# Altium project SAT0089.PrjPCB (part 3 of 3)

## Sheet CAMERA 6.SchDoc
size 431 x 279 mm; Date: Not shown in title block; ApprovedBy: Not shown in title block; CheckedBy: Not shown in title block; Author: Not shown in title block; CompanyName: Not shown in title block; DrawnBy: G. Fiolic; Engineer: Not shown in title block; Organization: Not shown in title block; Address1: Not shown in title block; Address2: Not shown in title block; Address3: Not shown in title block; Address4: Not shown in title block; DocumentNumber: 10; Revision: Use project parameter SCH_Rev; SheetNumber: 10; SheetTotal: 11; PageSetup: Record=PageOptions|CenterHorizontal=True|CenterVertical=True|PrintScale=1.00|XCorrection=1.00|YCorrection=1.00|PrintKind=0|BorderSize=5000000|LeftOffset=0|BottomOffset=0|Orientation=2|PaperLength=1000|PaperWidth=1000|Scale=100|PaperSource=15|PrintQuality=600|MediaType=1|DitherType=10|PaperKind=Letter|PrintScaleMode=1
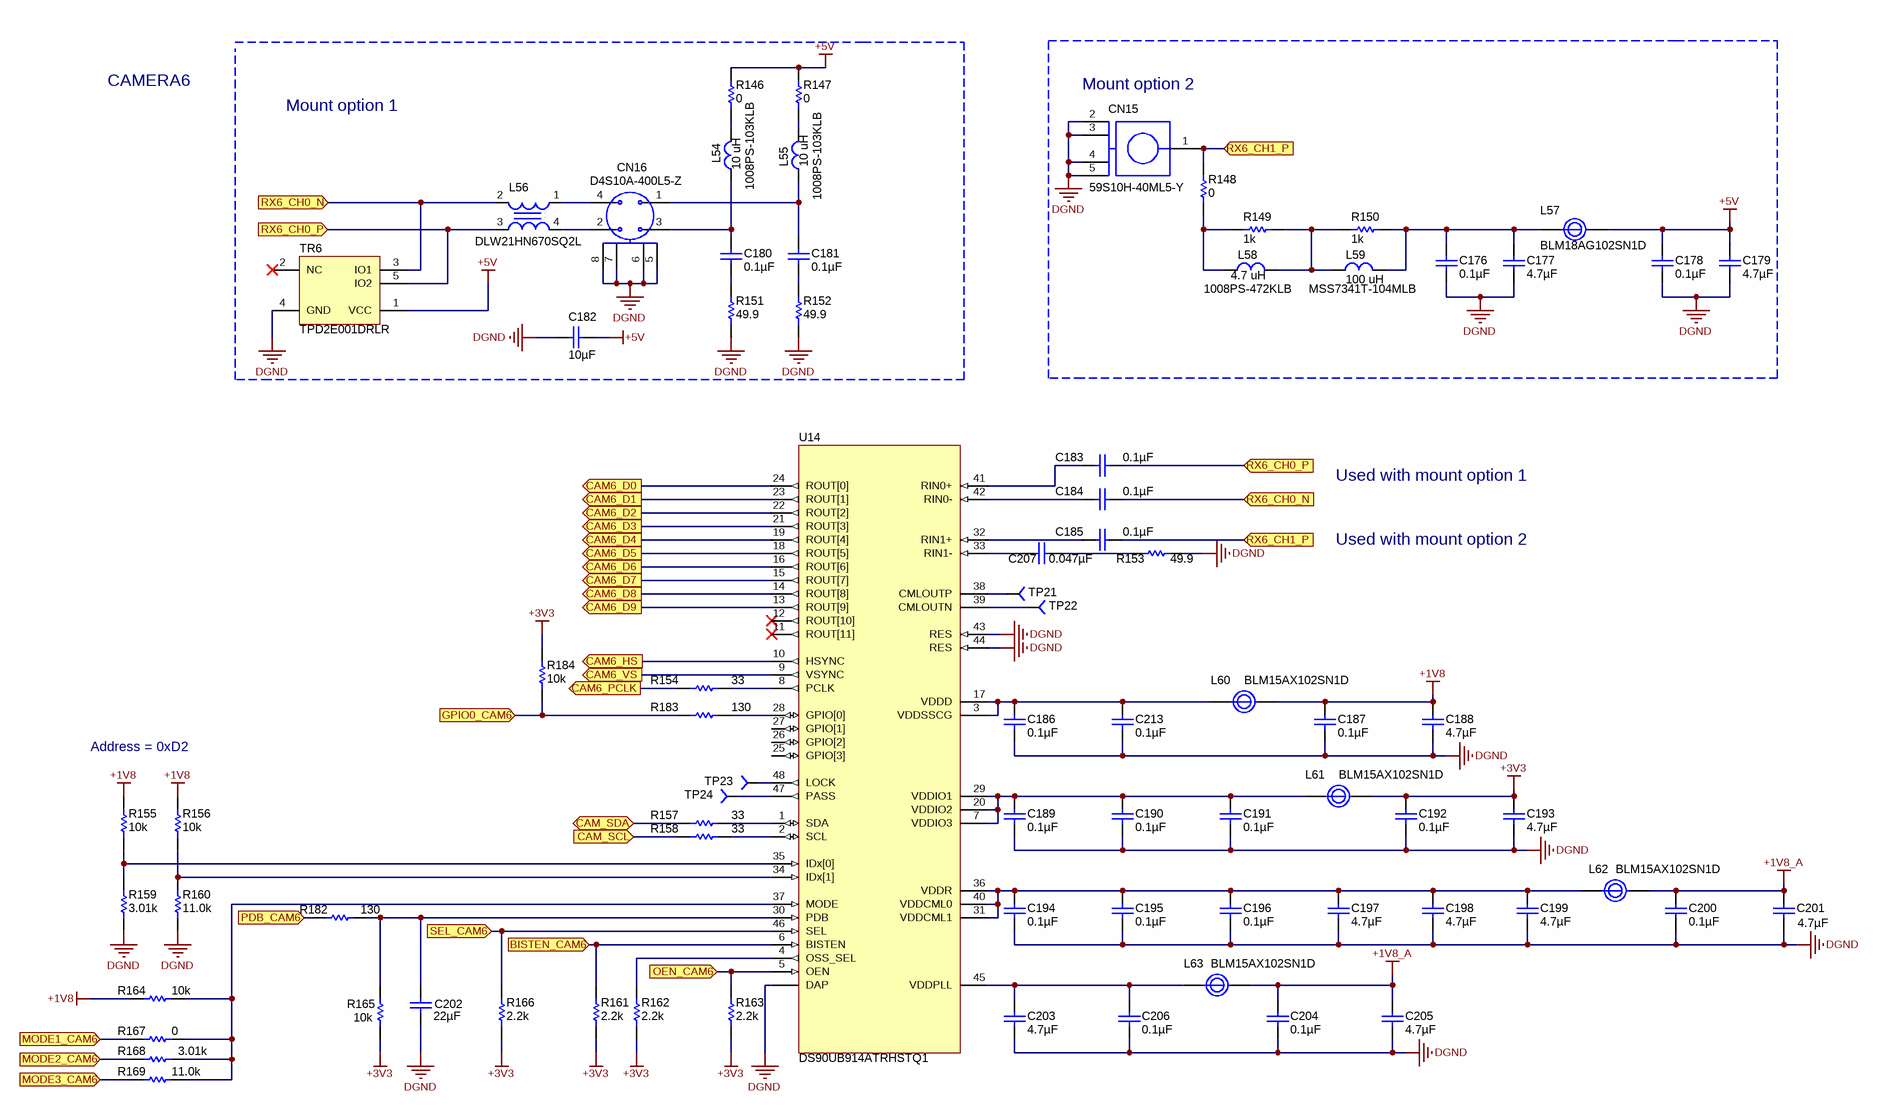
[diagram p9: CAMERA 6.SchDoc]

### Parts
C176  ValueDisplayed: 0.1µF  [0402L]  (hidden comment: GRM155R71C104KA88D)
C177  value 4.7µF  [0603L]  (hidden comment: GRM188R61E475KE11D)
C178  ValueDisplayed: 0.1µF  [0402L]  (hidden comment: GRM155R71C104KA88D)
C179  value 4.7µF  [0603L]  (hidden comment: GRM188R61E475KE11D)
C180  value 0.1µF  [0603L]  (hidden comment: GRM188R72A104KA35D)
C181  value 0.1µF  [0603L]  (hidden comment: GRM188R72A104KA35D)
C182  ValueDisplayed: 10µF  [0805L]  (hidden comment: GRM21BR61C106KE15L)
C183  ValueDisplayed: 0.1µF  [0402L]  (hidden comment: GRM155R71C104KA88D)
C184  ValueDisplayed: 0.1µF  [0402L]  (hidden comment: GRM155R71C104KA88D)
C185  ValueDisplayed: 0.1µF  [0402L]  (hidden comment: GRM155R71C104KA88D)
C186  ValueDisplayed: 0.1µF  [0402L]  (hidden comment: GRM155R71C104KA88D)
C187  ValueDisplayed: 0.1µF  [0402L]  (hidden comment: GRM155R71C104KA88D)
C188  value 4.7µF  [0603L]  (hidden comment: GRM188R61E475KE11D)
C189  ValueDisplayed: 0.1µF  [0402L]  (hidden comment: GRM155R71C104KA88D)
C190  ValueDisplayed: 0.1µF  [0402L]  (hidden comment: GRM155R71C104KA88D)
C191  ValueDisplayed: 0.1µF  [0402L]  (hidden comment: GRM155R71C104KA88D)
C192  ValueDisplayed: 0.1µF  [0402L]  (hidden comment: GRM155R71C104KA88D)
C193  value 4.7µF  [0603L]  (hidden comment: GRM188R61E475KE11D)
C194  ValueDisplayed: 0.1µF  [0402L]  (hidden comment: GRM155R71C104KA88D)
C195  ValueDisplayed: 0.1µF  [0402L]  (hidden comment: GRM155R71C104KA88D)
C196  ValueDisplayed: 0.1µF  [0402L]  (hidden comment: GRM155R71C104KA88D)
C197  value 4.7µF  [0603L]  (hidden comment: GRM188R61E475KE11D)
C198  value 4.7µF  [0603L]  (hidden comment: GRM188R61E475KE11D)
C199  value 4.7µF  [0603L]  (hidden comment: GRM188R61E475KE11D)
C200  ValueDisplayed: 0.1µF  [0402L]  (hidden comment: GRM155R71C104KA88D)
C201  value 4.7µF  [0603L]  (hidden comment: GRM188R61E475KE11D)
C202  ValueDisplayed: 22µF  [0805L]  (hidden comment: JMK212BJ226KG-T)
C203  value 4.7µF  [0603L]  (hidden comment: GRM188R61E475KE11D)
C204  ValueDisplayed: 0.1µF  [0402L]  (hidden comment: GRM155R71C104KA88D)
C205  value 4.7µF  [0603L]  (hidden comment: GRM188R61E475KE11D)
C206  ValueDisplayed: 0.1µF  [0402L]  (hidden comment: GRM155R71C104KA88D)
C207  ValueDisplayed: 0.047µF  [0402L]  (hidden comment: GRM155R71C473KA01D)
C213  ValueDisplayed: 0.1µF  [0402L]  (hidden comment: GRM155R71C104KA88D)
CN15  59S10H-40ML5-Y  [59S10H-40ML5-Y]
CN16  D4S10A-400L5-Z  [D4S10A-400L5-Z]
L54  1008PS-103KLB  ValueDisplayed: 10 uH  [1008PS-103KLB]
L55  1008PS-103KLB  ValueDisplayed: 10 uH  [1008PS-103KLB]
L56  DLW21HN670SQ2L  [DLW21HN670SQ2L]
L57  BLM18AG102SN1D  [0603L]
L58  ValueDisplayed: 4.7 uH  [1008PS-472KLB]  (hidden comment: 1008PS-472KLB)
L59  ValueDisplayed: 100 uH  [MSS7341T-104MLB]  (hidden comment: MSS7341T-104MLB)
L60  BLM15AX102SN1D  [0402L]
L61  BLM15AX102SN1D  [0402L]
L62  BLM15AX102SN1D  [0402L]
L63  BLM15AX102SN1D  [0402L]
R146  value 0  [0805L]  (hidden comment: CRCW08050000Z0EA)
R147  value 0  [0805L]  (hidden comment: CRCW08050000Z0EA)
R148  value 0  [0805L]  (hidden comment: CRCW08050000Z0EA)
R149  value 1k  [0603L]  (hidden comment: RC0603JR-071KL)
R150  value 1k  [0603L]  (hidden comment: RC0603JR-071KL)
R151  value 49.9  [0402L]  (hidden comment: CRCW040249R9FKED)
R152  value 49.9  [0402L]  (hidden comment: CRCW040249R9FKED)
R153  value 49.9  [0402L]  (hidden comment: CRCW040249R9FKED)
R154  value 33  [0402L]  (hidden comment: CRCW040233R0JNED)
R155  value 10k  [0402L]  (hidden comment: ERA-2AEB103X)
R156  value 10k  [0402L]  (hidden comment: ERA-2AEB103X)
R157  value 33  [0402L]  (hidden comment: CRCW040233R0JNED)
R158  value 33  [0402L]  (hidden comment: CRCW040233R0JNED)
R159  value 3.01k  [0402L]  (hidden comment: CRCW04023K01FKED)
R160  value 11.0k  [0402L]  (hidden comment: CRCW040211K0FKED)
R161  value 2.2k  [0402L]  (hidden comment: CRCW04022K20JNED)
R162  value 2.2k  [0402L]  (hidden comment: CRCW04022K20JNED)
R163  value 2.2k  [0402L]  (hidden comment: CRCW04022K20JNED)
R164  value 10k  [0402L]  (hidden comment: ERA-2AEB103X)
R165  value 10k  [0402L]  (hidden comment: ERA-2AEB103X)
R166  value 2.2k  [0402L]  (hidden comment: CRCW04022K20JNED)
R167  value 0  [0402L]  (hidden comment: CRCW04020000Z0ED)
R168  value 3.01k  [0402L]  (hidden comment: CRCW04023K01FKED)
R169  value 11.0k  [0402L]  (hidden comment: CRCW040211K0FKED)
R182  value 130  [0402L]  (hidden comment: CRCW0402130RJNED)
R183  value 130  [0402L]  (hidden comment: CRCW0402130RJNED)
R184  value 10k  [0402L]  (hidden comment: ERA-2AEB103X)
TP21  STD  [TP-032_RND]  (value not drawn)
TP22  STD  [TP-032_RND]  (value not drawn)
TP23  STD  [TP-032_RND]  (value not drawn)
TP24  STD  [TP-032_RND]  (value not drawn)
TR6  TPD2E001DRLR  [DRL0005A]
U14  DS90UB914ATRHSTQ1  [RHS0048A]

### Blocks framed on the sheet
Mount option 2: C176-C179 CN15 L57-L59 R148-R150

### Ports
BISTEN_CAM6, CAM6_D0, CAM6_D1, CAM6_D2, CAM6_D3, CAM6_D4, CAM6_D5, CAM6_D6, CAM6_D7, CAM6_D8, CAM6_D9, CAM6_HS, CAM6_PCLK, CAM6_VS, CAM_SCL, CAM_SDA, GPIO0_CAM6, MODE1_CAM6, MODE2_CAM6, MODE3_CAM6, OEN_CAM6, PDB_CAM6, RX6_CH0_N, RX6_CH0_P, RX6_CH1_P, SEL_CAM6

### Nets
+1V8: C187.1 C188.1 L60.2 R155.1 R156.1 R164.1
+1V8_A: C200.1 C201.1 C204.1 C205.1 L62.2 L63.2
+3V3: C192.1 C193.1 L61.2 R161.2 R162.2 R163.2 R165.1 R166.1 R184.1
+5V: C178.1 C179.1 C182.1 L57.2 R146.2 R147.2 TR6.1(VCC)
DGND: C176.2 C177.2 C178.2 C179.2 C182.2 C186.2 C187.2 C188.2 C189.2 C190.2 C191.2 C192.2 C193.2 C194.2 C195.2 C196.2 C197.2 C198.2 C199.2 C200.2 C201.2 C202.2 C203.2 C204.2 C205.2 C206.2 C213.2 CN15.2 CN15.3 CN15.4 CN15.5 CN16.5 CN16.6 CN16.7 CN16.8 R151.1 R152.1 R153.2 R159.2 R160.2 TR6.4(GND) U14.43(RES) U14.44(RES) U14.49(DAP)
BISTEN_CAM6: R161.1 U14.6(BISTEN) ; port BISTEN_CAM6
CAM6_D0: U14.24(ROUT[0]) ; port CAM6_D0
CAM6_D1: U14.23(ROUT[1]) ; port CAM6_D1
CAM6_D2: U14.22(ROUT[2]) ; port CAM6_D2
CAM6_D3: U14.21(ROUT[3]) ; port CAM6_D3
CAM6_D4: U14.19(ROUT[4]) ; port CAM6_D4
CAM6_D5: U14.18(ROUT[5]) ; port CAM6_D5
CAM6_D6: U14.16(ROUT[6]) ; port CAM6_D6
CAM6_D7: U14.15(ROUT[7]) ; port CAM6_D7
CAM6_D8: U14.14(ROUT[8]) ; port CAM6_D8
CAM6_D9: U14.13(ROUT[9]) ; port CAM6_D9
CAM6_HS: U14.10(HSYNC) ; port CAM6_HS
CAM6_PCLK: R154.1 ; port CAM6_PCLK
CAM6_VS: U14.9(VSYNC) ; port CAM6_VS
CAM_SCL: R158.1 ; port CAM_SCL
CAM_SDA: R157.2 ; port CAM_SDA
GPIO0_CAM6: R183.1 R184.2 ; port GPIO0_CAM6
MODE1_CAM6: R167.1 ; port MODE1_CAM6
MODE2_CAM6: R168.1 ; port MODE2_CAM6
MODE3_CAM6: R169.1 ; port MODE3_CAM6
OEN_CAM6: R163.1 U14.5(OEN) ; port OEN_CAM6
PDB_CAM6: R182.1 ; port PDB_CAM6
RX6_CH0_N: C184.2 L56.2(IN2) TR6.3(IO1) ; port RX6_CH0_N
RX6_CH0_P: C183.2 L56.3(OUT2) TR6.5(IO2) ; port RX6_CH0_P
RX6_CH1_P: C185.2 CN15.1 R148.2 ; port RX6_CH1_P
SEL_CAM6: R166.2 U14.46(SEL) ; port SEL_CAM6
NetC176_1: C176.1 C177.1 L57.1 L59.2 R150.2
NetC180_1: C180.1 CN16.3 L54.2
NetC180_2: C180.2 R151.2
NetC181_1: C181.1 CN16.1 L55.2
NetC181_2: C181.2 R152.2
NetC183_1: C183.1 U14.41(RIN0+)
NetC184_1: C184.1 U14.42(RIN0-)
NetC185_1: C185.1 U14.32(RIN1+)
NetC186_1: C186.1 C213.1 L60.1 U14.3(VDDSSCG) U14.17(VDDD)
NetC189_1: C189.1 C190.1 C191.1 L61.1 U14.7(VDDIO3) U14.20(VDDIO2) U14.29(VDDIO1)
NetC194_1: C194.1 C195.1 C196.1 C197.1 C198.1 C199.1 L62.1 U14.31(VDDCML1) U14.36(VDDR) U14.40(VDDCML0)
NetC202_1: C202.1 R165.2 R182.2 U14.30(PDB)
NetC203_1: C203.1 C206.1 L63.1 U14.45(VDDPLL)
NetC207_1: C207.1 U14.33(RIN1-)
NetC207_2: C207.2 R153.1
NetCN16_2: CN16.2 L56.4(OUT1)
NetCN16_4: CN16.4 L56.1(IN1)
NetL54_1: L54.1 R146.1
NetL55_1: L55.1 R147.1
NetL58_1: L58.1 R148.1 R149.1
NetL58_2: L58.2 L59.1 R149.2 R150.1
NetR154_2: R154.2 U14.8(PCLK)
NetR155_2: R155.2 R159.1 U14.35(IDx[0])
NetR156_2: R156.2 R160.1 U14.34(IDx[1])
NetR157_1: R157.1 U14.1(SDA)
NetR158_2: R158.2 U14.2(SCL)
NetR162_1: R162.1 U14.4(OSS_SEL)
NetR164_2: R164.2 R167.2 R168.2 R169.2 U14.37(MODE)
NetR183_2: R183.2 U14.28(GPIO[0])
NetTP21_1: TP21.1 U14.38(CMLOUTP)
NetTP22_1: TP22.1 U14.39(CMLOUTN)
NetTP23_1: TP23.1 U14.48(LOCK)
NetTP24_1: TP24.1 U14.47(PASS)

Not connected (* = marked no-connect by the designer): TR6 2(NC)*; U14 11(ROUT[11])* 12(ROUT[10])* 25(GPIO[3]) 26(GPIO[2]) 27(GPIO[1])

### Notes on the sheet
- CAMERA6
- Mount option 1
- Used with mount option 1
- Used with mount option 2
- Address = 0xD2

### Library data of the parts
C176 C178 C183-C187 C189-C192 C194-C196 C200 C204 C206 C213 = GRM155R71C104KA88D: CAP, CERM, 0.1uF, 16V, +/-10%, X7R, 0402; Manufacturer: MuRata; Polarized: N; CompType: Capacitor; U/M: EA; Cap_F: 0.0000001; Tolerance_%: 10; Value1: Unknown; VDC_V: 16; TaMin_C: -55; TaMax_C: 125; Cap_Case: 0402
C177 C179 C188 C193 C197-C199 C201 C203 C205 = GRM188R61E475KE11D: CAP CER 4.7UF 25V 10% X5R 0603; Manufacturer: Murata Electronics North America
C180 C181 = GRM188R72A104KA35D: CAP CER 0.1UF 100V 10% X7R 0603; Manufacturer: Murata Electronics North America
C182 = GRM21BR61C106KE15L: CAP, CERM, 10uF, 16V, +/-10%, X5R, 0805; Manufacturer: MuRata; Polarized: N; CompType: Capacitor; U/M: EA; Cap_F: 0.00001; Tolerance_%: 10; ESR_Ohm: 0.008; Value1: 0.008 ohm; VDC_V: 16; TaMin_C: -55; TaMax_C: 85; Cap_Case: 0805
C202 = JMK212BJ226KG-T: CAP, CERM, 22uF, 6.3V, +/-10%, X5R, 0805; Manufacturer: Taiyo Yuden; Polarized: N; CompType: Capacitor; U/M: EA; Cap_F: 0.000022; Tolerance_%: 10; ESR_Ohm: 0.002; Value1: 0.002 ohm; VDC_V: 6.3; TaMin_C: -55; TaMax_C: 85; Cap_Case: 0805
C207 = GRM155R71C473KA01D: CAP, CERM, 0.047uF, 16V, +/-10%, X7R, 0402; Manufacturer: MuRata; Polarized: N; CompType: Capacitor; U/M: EA; Cap_F: 0.000000047; Tolerance_%: 10; Value1: Unknown; VDC_V: 16; TaMin_C: -55; TaMax_C: 125; Cap_Case: 0402
CN15 = 59S10H-40ML5-Y: Straight Plug PCB; Manufacturer: Rosenberger; SymbolVersion: use current date i.e. 2008-05-20; SymbolCreator: Use a-id; CompType: SMA connector; U/M: EA, IN, or GM
CN16 = D4S10A-400L5-Z: Straight Plug; Manufacturer: Rosenberger
L54 L55 = 1008PS-103KLB: Fixed Inductors Power Inductor 10 uH 10 % 0.59 A; Manufacturer: Coilcraft; Material: Ferrite; Maximum DC Current: 590 mA; Maximum DC Resistance: 920 mOhms; Q Minimum: 38; Self Resonant Frequency: 105 MHz; Shielding: Shielded; Tolerance_%: 10 %; Case Height: 2.74 mm; Case Length: 3.81 mm; Case Width: 3.78 mm; Test Frequency: 100 kHz; Product Status: New at Mouser
L56 = DLW21HN670SQ2L: CHOKE COMMON MODE 67 OHM 0805; Manufacturer: Murata Electronics North America; Filter Type: Data, Signal Line; Number of Lines: 2; Irms: 330mA; DCR_Ohm: 350 mOhm Max; Impedance: 67 Ohm
L57 = BLM18AG102SN1D: FERRITE CHIP 1000 OHM 400MA 0603; Manufacturer: Murata Electronics North America; Impedance @ Frequency: 1 kOhm @ 100MHz; DCR_Ohm: 500 mOhm Max; Filter Type: Differential Mode - Single
L58 = 1008PS-472KLB: Fixed Inductors Power Inductor 4.7 uH 10 % 0.95 A; Manufacturer: Coilcraft; Material: Ferrite; Maximum DC Current: 950 mA; Maximum DC Resistance: 350 mOhms; Q Minimum: 38; Self Resonant Frequency: 160 MHz; Shielding: Shielded; Tolerance_%: 10 %; Case Height: 2.74 mm; Case Length: 3.81 mm; Case Width: 3.78 mm; Test Frequency: 100 kHz
L59 = MSS7341T-104MLB: Fixed Inductors Power Inductor 100 uH 20 % 1.15 A; Manufacturer: Coilcraft; Material: Ferrite; Maximum DC Current: 1.15 A; Maximum DC Resistance: 310 mOhms; Self Resonant Frequency: 7.2 MHz; Shielding: Shielded; Tolerance_%: 20 %; Case Height: 4.1 mm; Case Length: 7.3 mm; Test Frequency: 100 kHz
L60-L63 = BLM15AX102SN1D: FERRITE CHIP 1000 OHM 0402; Manufacturer: Murata Electronics North America; Impedance @ Frequency: 1 kOhm @ 100MHz; Current Rating: 350mA; DCR_Ohm: 490 mOhm Max; Filter Type: Differential Mode - Single
R146-R148 = CRCW08050000Z0EA: RES, 0 ohm, 5%, 0.125W, 0805; Manufacturer: Vishay-Dale; CompType: Resistor; Value_Code: 0000; Tolerance_%: 5; Power_W: 0.125; VDC_V: 150; TempCo: 200 ppm/C; EIA_Code: E24; U/M: EA
R149 R150 = RC0603JR-071KL: RES 1.0K OHM 1/10W 5% 0603 SMD; Manufacturer: Yageo; Power_W: 0.1W, 1/10W; TempCo: ±100ppm/°C
R151-R153 = CRCW040249R9FKED: RES, 49.9 ohm, 1%, 0.063W, 0402; Manufacturer: Vishay-Dale; CompType: Resistor; Value_Code: 49R9; Tolerance_%: 1; Power_W: 0.063; VDC_V: 50; TempCo: 100 ppm/C; EIA_Code: E96; U/M: EA
R154 R157 R158 = CRCW040233R0JNED: RES, 33 ohm, 5%, 0.063W, 0402; Manufacturer: Vishay-Dale; CompType: Resistor; Value_Code: 33R0; Tolerance_%: 5; Power_W: 0.063; VDC_V: 50; TempCo: 200 ppm/C; EIA_Code: E24; U/M: EA
R155 R156 R164 R165 R184 = ERA-2AEB103X: RES 10K OHM 1/16W .1% 0402 SMD; Manufacturer: Panasonic Electronic Components; Tolerance_%: ±0.1%; Power_W: 0.063W, 1/16W; TempCo: ±25ppm/°C
R159 R168 = CRCW04023K01FKED: RES, 3.01k ohm, 1%, 0.063W, 0402; Manufacturer: Vishay-Dale; CompType: Resistor; Res_ohm: 3010; Value_Code: 3k01; Tolerance_%: 1; Power_W: 0.063; VDC_V: 50; TempCo: 100 ppm/C; EIA_Code: E96; U/M: EA
R160 R169 = CRCW040211K0FKED: RES, 11.0k ohm, 1%, 0.063W, 0402; Manufacturer: Vishay-Dale; CompType: Resistor; Res_ohm: 11000; Value_Code: 11k0; Tolerance_%: 1; Power_W: 0.063; VDC_V: 50; TempCo: 100 ppm/C; EIA_Code: E96; U/M: EA
R161-R163 R166 = CRCW04022K20JNED: RES, 2.2k ohm, 5%, 0.063W, 0402; Manufacturer: Vishay-Dale; CompType: Resistor; Res_ohm: 2200; Value_Code: 2k20; Tolerance_%: 5; Power_W: 0.063; VDC_V: 50; TempCo: 200 ppm/C; EIA_Code: E24; U/M: EA
R167 = CRCW04020000Z0ED: RES, 0 ohm, 5%, 0.063W, 0402; Manufacturer: Vishay-Dale; CompType: Resistor; Value_Code: 0000; Tolerance_%: 5; Power_W: 0.063; VDC_V: 50; TempCo: 200 ppm/C; EIA_Code: E24; U/M: EA
R182 R183 = CRCW0402130RJNED: RES, 130 ohm, 5%, 0.063W, 0402; Manufacturer: Vishay-Dale; CompType: Resistor; Value_Code: 130R; Tolerance_%: 5; Power_W: 0.063; VDC_V: 50; TempCo: 200 ppm/C; EIA_Code: E24; U/M: EA
TP21-TP24 = TP-032_RND: Test Point, O.032 Hole
TR6 = TPD2E001DRLR: Low-Capacitance + / - 15 kV ESD-Protection Array for High-Speed Data Interfaces, 2 Channels, -40 to +85 degC, 5-pin SOT (DRL), Green (RoHS & no Sb/Br); Manufacturer: Texas Instruments; Alternate Manufacturer: None; Alternate PartNumber: Equivalent; Breakdown Voltage(Min)(V): 11; IEC 61000-4-2 Air-Gap(+/- kV): 15; IEC 61000-4-2 Contact(+/- kV): 8; IO Capacitance(Typ)(pF): 1.5; IO Leakage Current(nA): 1; SubFamily: ESD Solution; USB High Speed: TRUE
U14 = DS90UB914ATRHSTQ1: FPD-Link III Serializer and Deserializer, RHS0048A; Alternate Manufacturer: None; Manufacturer: Texas Instruments; SymbolCreator: a0799628; CompType: IC; U/M: EA

## Sheet Hardware_ANSI-B.SchDoc
size 431 x 279 mm; Date: Not shown in title block; ApprovedBy: Not shown in title block; CheckedBy: Not shown in title block; Author: Not shown in title block; CompanyName: Not shown in title block; DrawnBy: G. Fiolic; Engineer: Not shown in title block; Organization: Not shown in title block; Address1: Not shown in title block; Address2: Not shown in title block; Address3: Not shown in title block; Address4: Not shown in title block; DocumentNumber: 11; Revision: Use project parameter SCH_Rev; SheetNumber: 11; SheetTotal: 11; PageSetup: Record=PageOptions|CenterHorizontal=True|CenterVertical=True|PrintScale=1.00|XCorrection=1.00|YCorrection=1.00|PrintKind=0|BorderSize=5000000|LeftOffset=0|BottomOffset=0|Orientation=2|PaperLength=1000|PaperWidth=1000|Scale=100|PaperSource=15|PrintQuality=600|MediaType=1|DitherType=10|PaperKind=Letter|PrintScaleMode=1
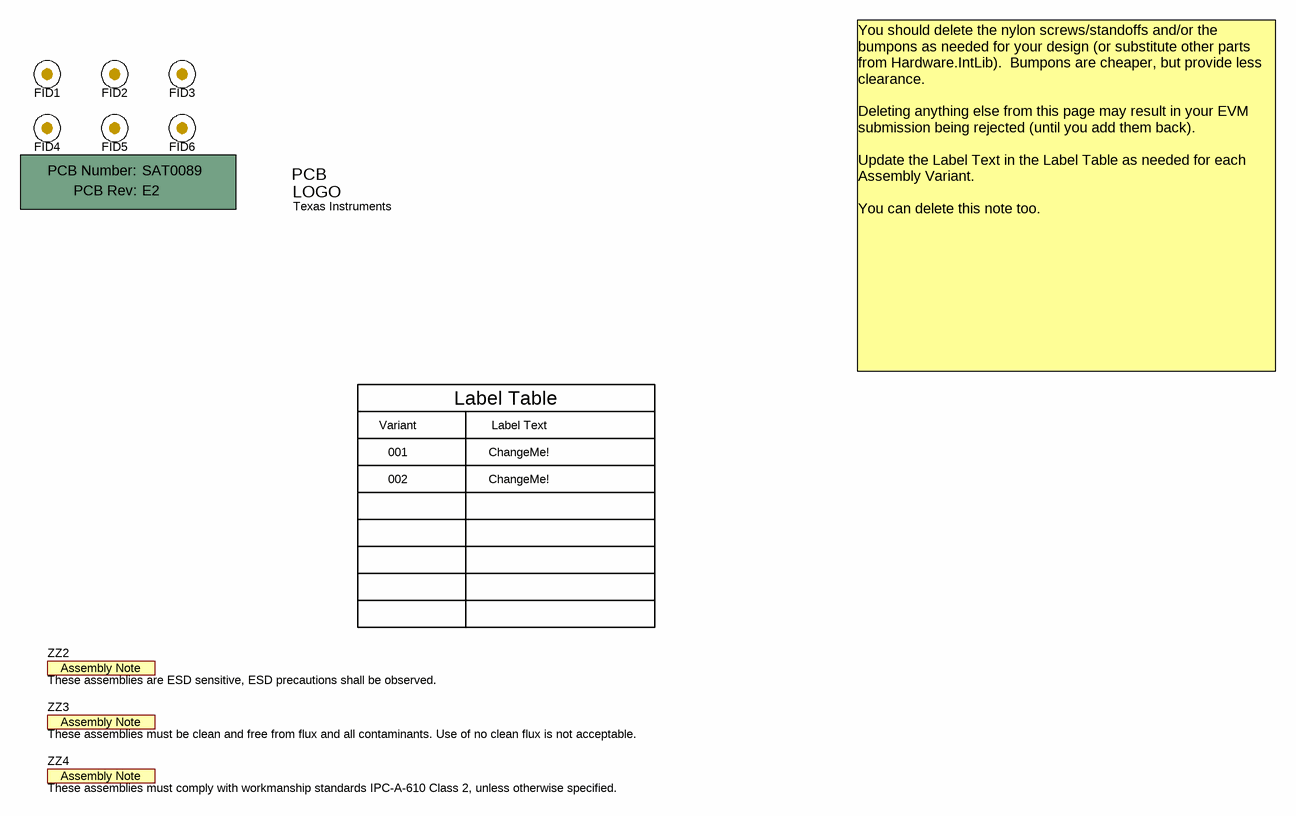
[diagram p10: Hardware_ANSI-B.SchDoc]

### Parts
!PCB  Printed Circuit Board  (value not drawn)  (mechanical)
FID1  Fiducial  [Fiducial10-20]  (value not drawn)
FID2  Fiducial  [Fiducial10-20]  (value not drawn)
FID3  Fiducial  [Fiducial10-20]  (value not drawn)
FID4  Fiducial  [Fiducial10-20]  (value not drawn)
FID5  Fiducial  [Fiducial10-20]  (value not drawn)
FID6  Fiducial  [Fiducial10-20]  (value not drawn)
Logo1  Texas Instruments  [TI_Symbol_Overlay_Medium]  (no BOM)
ZZ2  These assemblies are ESD sensitive, ESD precautions shall be observed.  [AssemblyNote]  (no BOM)
ZZ3  These assemblies must be clean and free from flux and all contaminants. Use of no clean flux is not acceptable.  [AssemblyNote]  (no BOM)
ZZ4  These assemblies must comply with workmanship standards IPC-A-610 Class 2, unless otherwise specified.  [AssemblyNote]  (no BOM)

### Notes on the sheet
- Variant
- Label Table
- Label Text
- You should delete the nylon screws/standoffs and/or the bumpons as needed for your design (or substitute other parts from Hardware.IntLib).  Bumpons are cheaper, but provide less clearance.
  Deleting anything else from this page may result in your EVM submission being rejected (until you add them back).
  Update the Label Text in the Label Table as needed for each Assembly Variant.
  You can delete this note too.
- 001
- 002
- ChangeMe!

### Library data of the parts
!PCB = PCB: Manufacturer: Any; PartNumber: SAT0089; SymbolCreator: a0412235
FID1-FID6 = Fiducial: Fiducial mark.  There is nothing to buy or mount.; SymbolCreator: codlsc
Logo1 = TI_Logo: Texas Instrument Corporate Signature; SymbolCreator: codlsc
ZZ2-ZZ4 = AssemblyNote: SymbolCreator: codlsc

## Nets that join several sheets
+1V8: POWER (C12.1 L2.2 U7.4), CAMERA 1 (6 pins), CAMERA 2 (6 pins), CAMERA 3 (6 pins), CAMERA 4 (6 pins), CAMERA 5 (6 pins), CAMERA 6 (6 pins)
+1V8_A: POWER (C13.1 L3.2 U8.4), CAMERA 1 (6 pins), CAMERA 2 (6 pins), CAMERA 3 (6 pins), CAMERA 4 (6 pins), CAMERA 5 (6 pins), CAMERA 6 (6 pins)
+3V3: MAIN_CONNECTORS (5 pins), COMMON (16 pins), CAMERA 1 (9 pins), CAMERA 2 (9 pins), CAMERA 3 (9 pins), CAMERA 4 (9 pins), CAMERA 5 (9 pins), CAMERA 6 (9 pins)
+5V: POWER (12 pins), CAMERA 1 (7 pins), CAMERA 2 (7 pins), CAMERA 3 (7 pins), CAMERA 4 (7 pins), CAMERA 5 (7 pins), CAMERA 6 (7 pins)
DGND: POWER (23 pins), MAIN_CONNECTORS (63 pins), COMMON (18 pins), CAMERA 1 (44 pins), CAMERA 2 (44 pins), CAMERA 3 (44 pins), CAMERA 4 (44 pins), CAMERA 5 (44 pins), CAMERA 6 (44 pins)
VDD_12V: POWER (C7.1 C8.1 C9.1 U6.2), MAIN_CONNECTORS (CN1.35 CN1.37)
BISTEN_CAM1: COMMON (U1.19), CAMERA 1 (R41.1 U9.6)
BISTEN_CAM2: COMMON (U1.4), CAMERA 2 (R65.1 U10.6)
BISTEN_CAM3: COMMON (U4.19), CAMERA 3 (R89.1 U11.6)
BISTEN_CAM4: COMMON (U4.4 U4.6), CAMERA 4 (R113.1 R118.2 U12.6 U12.46)
BISTEN_CAM5: COMMON (U5.19), CAMERA 5 (R137.1 U13.6)
BISTEN_CAM6: COMMON (U5.4), CAMERA 6 (R161.1 U14.6)
CAM1_D0: COMMON (CN2.1), CAMERA 1 (U9.24)
CAM1_D0_CAM1_VS: MAIN_CONNECTORS (CN1.133), COMMON (CN2.7)
CAM1_D1: MAIN_CONNECTORS (CN1.95), CAMERA 1 (U9.23)
CAM1_D2: MAIN_CONNECTORS (CN1.131), CAMERA 1 (U9.22)
CAM1_D3: MAIN_CONNECTORS (CN1.130), CAMERA 1 (U9.21)
CAM1_D4: MAIN_CONNECTORS (CN1.90), CAMERA 1 (U9.19)
CAM1_D5: MAIN_CONNECTORS (CN1.89), CAMERA 1 (U9.18)
CAM1_D6: MAIN_CONNECTORS (CN1.140), CAMERA 1 (U9.16)
CAM1_D7: MAIN_CONNECTORS (CN1.139), CAMERA 1 (U9.15)
CAM1_D8: MAIN_CONNECTORS (CN1.58), CAMERA 1 (U9.14)
CAM1_D9: MAIN_CONNECTORS (CN1.57), CAMERA 1 (U9.13)
CAM1_D10: COMMON (CN3.14), CAMERA 1 (U9.12)
CAM1_D11: COMMON (CN3.15), CAMERA 1 (U9.11)
CAM1_HS: MAIN_CONNECTORS (CN1.96), CAMERA 1 (U9.10)
CAM1_PCLK: MAIN_CONNECTORS (CN1.87), CAMERA 1 (R32.1)
CAM1_VS: COMMON (CN2.13 CN3.13), CAMERA 1 (U9.9)
CAM2_D0: COMMON (CN2.2), CAMERA 2 (U10.24)
CAM2_D0_CAM2_VS: MAIN_CONNECTORS (CN1.134), COMMON (CN2.8)
CAM2_D1: MAIN_CONNECTORS (CN1.51), CAMERA 2 (U10.23)
CAM2_D2: MAIN_CONNECTORS (CN1.49), CAMERA 2 (U10.22)
CAM2_D3: MAIN_CONNECTORS (CN1.48), CAMERA 2 (U10.21)
CAM2_D4: MAIN_CONNECTORS (CN1.125), CAMERA 2 (U10.19)
CAM2_D5: MAIN_CONNECTORS (CN1.124), CAMERA 2 (U10.18)
CAM2_D6: MAIN_CONNECTORS (CN1.15), CAMERA 2 (U10.16)
CAM2_D7: MAIN_CONNECTORS (CN1.14), CAMERA 2 (U10.15)
CAM2_D8: MAIN_CONNECTORS (CN1.128), CAMERA 2 (U10.14)
CAM2_D9: MAIN_CONNECTORS (CN1.127), CAMERA 2 (U10.13)
CAM2_D10: COMMON (CN3.17), CAMERA 2 (U10.12)
CAM2_D11: COMMON (CN3.18), CAMERA 2 (U10.11)
CAM2_HS: MAIN_CONNECTORS (CN1.52), CAMERA 2 (U10.10)
CAM2_PCLK: MAIN_CONNECTORS (CN1.86), CAMERA 2 (R58.1)
CAM2_VS: COMMON (CN2.14 CN3.16), CAMERA 2 (U10.9)
CAM3_D0: COMMON (CN2.3), CAMERA 3 (U11.24)
CAM3_D0_CAM3_VS: MAIN_CONNECTORS (CN1.142), COMMON (CN2.9)
CAM3_D1: MAIN_CONNECTORS (CN1.110), CAMERA 3 (U11.23)
CAM3_D2: MAIN_CONNECTORS (CN1.11), CAMERA 3 (U11.22)
CAM3_D3: MAIN_CONNECTORS (CN1.10), CAMERA 3 (U11.21)
CAM3_D4: MAIN_CONNECTORS (CN1.102), CAMERA 3 (U11.19)
CAM3_D5: MAIN_CONNECTORS (CN1.101), CAMERA 3 (U11.18)
CAM3_D6: MAIN_CONNECTORS (CN1.105), CAMERA 3 (U11.16)
CAM3_D7: MAIN_CONNECTORS (CN1.104), CAMERA 3 (U11.15)
CAM3_D8: MAIN_CONNECTORS (CN1.64), CAMERA 3 (U11.14)
CAM3_D9: MAIN_CONNECTORS (CN1.63), CAMERA 3 (U11.13)
CAM3_D10: COMMON (CN4.14), CAMERA 3 (U11.12)
CAM3_D11: COMMON (CN4.15), CAMERA 3 (U11.11)
CAM3_HS: MAIN_CONNECTORS (CN1.111), CAMERA 3 (U11.10)
CAM3_PCLK: MAIN_CONNECTORS (CN1.61), CAMERA 3 (R82.1)
CAM3_VS: COMMON (CN2.15 CN4.13), CAMERA 3 (U11.9)
CAM4_D0: COMMON (CN2.4), CAMERA 4 (U12.24)
CAM4_D0_CAM4_VS: MAIN_CONNECTORS (CN1.143), COMMON (CN2.10)
CAM4_D1: MAIN_CONNECTORS (CN1.157), CAMERA 4 (U12.23)
CAM4_D2: MAIN_CONNECTORS (CN1.155), CAMERA 4 (U12.22)
CAM4_D3: MAIN_CONNECTORS (CN1.154), CAMERA 4 (U12.21)
CAM4_D4: MAIN_CONNECTORS (CN1.108), CAMERA 4 (U12.19)
CAM4_D5: MAIN_CONNECTORS (CN1.107), CAMERA 4 (U12.18)
CAM4_D6: MAIN_CONNECTORS (CN1.152), CAMERA 4 (U12.16)
CAM4_D7: MAIN_CONNECTORS (CN1.151), CAMERA 4 (U12.15)
CAM4_D8: MAIN_CONNECTORS (CN1.67), CAMERA 4 (U12.14)
CAM4_D9: MAIN_CONNECTORS (CN1.66), CAMERA 4 (U12.13)
CAM4_D10: COMMON (CN4.17), CAMERA 4 (U12.12)
CAM4_D11: COMMON (CN4.18), CAMERA 4 (U12.11)
CAM4_HS: MAIN_CONNECTORS (CN1.158), CAMERA 4 (U12.10)
CAM4_PCLK: MAIN_CONNECTORS (CN1.60), CAMERA 4 (R106.1)
CAM4_VS: COMMON (CN2.16 CN4.16), CAMERA 4 (U12.9)
CAM5_D0: COMMON (CN2.5), CAMERA 5 (U13.24)
CAM5_D0_CAM5_VS: MAIN_CONNECTORS (CN1.145), COMMON (CN2.11)
CAM5_D1: COMMON (CN3.1), CAMERA 5 (U13.23)
CAM5_D1_CAM1_VS: MAIN_CONNECTORS (CN1.82), COMMON (CN3.7)
CAM5_D2: COMMON (CN3.2), CAMERA 5 (U13.22)
CAM5_D2_CAM1_D10: MAIN_CONNECTORS (CN1.83), COMMON (CN3.8)
CAM5_D3: COMMON (CN3.3), CAMERA 5 (U13.21)
CAM5_D3_CAM1_D11: MAIN_CONNECTORS (CN1.92), COMMON (CN3.9)
CAM5_D4: COMMON (CN3.4), CAMERA 5 (U13.19)
CAM5_D4_CAM2_VS: MAIN_CONNECTORS (CN1.93), COMMON (CN3.10)
CAM5_D5: COMMON (CN3.5), CAMERA 5 (U13.18)
CAM5_D5_CAM2_D10: MAIN_CONNECTORS (CN1.98), COMMON (CN3.11)
CAM5_D6: COMMON (CN3.6), CAMERA 5 (U13.16)
CAM5_D6_CAM2_D11: MAIN_CONNECTORS (CN1.99), COMMON (CN3.12)
CAM5_D7: MAIN_CONNECTORS (CN1.113), CAMERA 5 (U13.15)
CAM5_D8: MAIN_CONNECTORS (CN1.114), CAMERA 5 (U13.14)
CAM5_D9: MAIN_CONNECTORS (CN1.116), CAMERA 5 (U13.13)
CAM5_HS: MAIN_CONNECTORS (CN1.26), CAMERA 5 (U13.10)
CAM5_PCLK: MAIN_CONNECTORS (CN1.23), CAMERA 5 (R130.1)
CAM5_VS: COMMON (CN2.17), CAMERA 5 (U13.9)
CAM6_D0: COMMON (CN2.6), CAMERA 6 (U14.24)
CAM6_D0_CAM6_VS: MAIN_CONNECTORS (CN1.146), COMMON (CN2.12)
CAM6_D1: COMMON (CN4.1), CAMERA 6 (U14.23)
CAM6_D1_CAM3_VS: MAIN_CONNECTORS (CN1.54), COMMON (CN4.7)
CAM6_D2: COMMON (CN4.2), CAMERA 6 (U14.22)
CAM6_D2_CAM3_D10: MAIN_CONNECTORS (CN1.55), COMMON (CN4.8)
CAM6_D3: COMMON (CN4.3), CAMERA 6 (U14.21)
CAM6_D3_CAM3_D11: MAIN_CONNECTORS (CN1.18), COMMON (CN4.9)
CAM6_D4: COMMON (CN4.4), CAMERA 6 (U14.19)
CAM6_D4_CAM4_VS: MAIN_CONNECTORS (CN1.19), COMMON (CN4.10)
CAM6_D5: COMMON (CN4.5), CAMERA 6 (U14.18)
CAM6_D5_CAM4_D10: MAIN_CONNECTORS (CN1.27), COMMON (CN4.11)
CAM6_D6: COMMON (CN4.6), CAMERA 6 (U14.16)
CAM6_D6_CAM4_D11: MAIN_CONNECTORS (CN1.137), COMMON (CN4.12)
CAM6_D7: MAIN_CONNECTORS (CN1.148), CAMERA 6 (U14.15)
CAM6_D8: MAIN_CONNECTORS (CN1.149), CAMERA 6 (U14.14)
CAM6_D9: MAIN_CONNECTORS (CN1.117), CAMERA 6 (U14.13)
CAM6_HS: MAIN_CONNECTORS (CN1.136), CAMERA 6 (U14.10)
CAM6_PCLK: MAIN_CONNECTORS (CN1.22), CAMERA 6 (R154.1)
CAM6_VS: COMMON (CN2.18), CAMERA 6 (U14.9)
CAM_SCL: MAIN_CONNECTORS (CN1.30), COMMON (5 pins), CAMERA 1 (R37.1), CAMERA 2 (R62.1), CAMERA 3 (R86.1), CAMERA 4 (R110.1), CAMERA 5 (R134.1), CAMERA 6 (R158.1)
CAM_SDA: MAIN_CONNECTORS (CN1.31), COMMON (5 pins), CAMERA 1 (R36.2), CAMERA 2 (R61.2), CAMERA 3 (R85.2), CAMERA 4 (R109.2), CAMERA 5 (R133.2), CAMERA 6 (R157.2)
FMC_GA0: MAIN_CONNECTORS (CN1.34), COMMON (R5.1)
FMC_GA1: MAIN_CONNECTORS (CN1.75), COMMON (R6.2)
GPIO0_CAM1: COMMON (U1.18), CAMERA 1 (R31.2 R33.1)
GPIO0_CAM2: COMMON (U1.3), CAMERA 2 (R171.1 R172.2)
GPIO0_CAM3: COMMON (U4.18), CAMERA 3 (R174.1 R175.2)
GPIO0_CAM4: COMMON (U4.3), CAMERA 4 (R177.1 R178.2)
GPIO0_CAM5: COMMON (U5.18), CAMERA 5 (R180.1 R181.2)
GPIO0_CAM6: COMMON (U5.3), CAMERA 6 (R183.1 R184.2)
MODE1_CAM1: COMMON (U1.15), CAMERA 1 (R45.1)
MODE1_CAM2: COMMON (U1.24), CAMERA 2 (R71.1)
MODE1_CAM3: COMMON (U4.15), CAMERA 3 (R95.1)
MODE1_CAM4: COMMON (U4.24), CAMERA 4 (R119.1)
MODE1_CAM5: COMMON (U5.15), CAMERA 5 (R143.1)
MODE1_CAM6: COMMON (U5.24), CAMERA 6 (R167.1)
MODE2_CAM1: COMMON (U1.16), CAMERA 1 (R48.1)
MODE2_CAM2: COMMON (U1.1), CAMERA 2 (R72.1)
MODE2_CAM3: COMMON (U4.16), CAMERA 3 (R96.1)
MODE2_CAM4: COMMON (U4.1), CAMERA 4 (R120.1)
MODE2_CAM5: COMMON (U5.16), CAMERA 5 (R144.1)
MODE2_CAM6: COMMON (U5.1), CAMERA 6 (R168.1)
MODE3_CAM1: COMMON (U1.17), CAMERA 1 (R49.1)
MODE3_CAM2: COMMON (U1.2), CAMERA 2 (R73.1)
MODE3_CAM3: COMMON (U4.17), CAMERA 3 (R97.1)
MODE3_CAM4: COMMON (U4.2), CAMERA 4 (R121.1)
MODE3_CAM5: COMMON (U5.17), CAMERA 5 (R145.1)
MODE3_CAM6: COMMON (U5.2), CAMERA 6 (R169.1)
OEN_CAM1: COMMON (U1.20), CAMERA 1 (R43.1 U9.5)
OEN_CAM2: COMMON (U1.5), CAMERA 2 (R67.1 U10.5)
OEN_CAM3: COMMON (U4.20), CAMERA 3 (R91.1 U11.5)
OEN_CAM4: COMMON (U4.5), CAMERA 4 (R115.1 U12.5)
OEN_CAM5: COMMON (U5.20), CAMERA 5 (R139.1 U13.5)
OEN_CAM6: COMMON (U5.5), CAMERA 6 (R163.1 U14.5)
PDB_CAM1: COMMON (U1.22), CAMERA 1 (R40.1)
PDB_CAM2: COMMON (U1.7), CAMERA 2 (R170.1)
PDB_CAM3: COMMON (U4.22), CAMERA 3 (R173.1)
PDB_CAM4: COMMON (U4.7), CAMERA 4 (R176.1)
PDB_CAM5: COMMON (U5.22), CAMERA 5 (R179.1)
PDB_CAM6: COMMON (U5.7), CAMERA 6 (R182.1)
SEL_CAM1: COMMON (U1.21), CAMERA 1 (R46.2 U9.46)
SEL_CAM2: COMMON (U1.6), CAMERA 2 (R70.2 U10.46)
SEL_CAM3: COMMON (U4.21), CAMERA 3 (R94.2 U11.46)
SEL_CAM5: COMMON (U5.21), CAMERA 5 (R142.2 U13.46)
SEL_CAM6: COMMON (U5.6), CAMERA 6 (R166.2 U14.46)

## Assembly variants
001: not fitted FID1 FID2 FID3 FID4 FID5 FID6 R20 R22 R45 R48 R71 R72 R95 R96 R119 R120 R143 R144 R167 R168 TR1 TR2 TR3 TR4 TR5 TR6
